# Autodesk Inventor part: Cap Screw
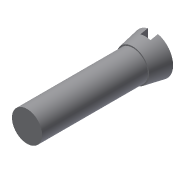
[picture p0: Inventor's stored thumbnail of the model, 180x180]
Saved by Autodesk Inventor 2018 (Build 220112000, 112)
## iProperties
Shininess: 77.0
Length Units: 11269
Angle Units: 11279
Time Units: 11290
Mass Units: 11283
Length Display Precision: 3
Angle Display Precision: 2
Created: 2002-02
Part Number: Cap Screw
Document SubType Name: Modeling
Designer: ***
Density: 1 g/cm^3
Material: Generic
Mass: 0.736586 g
Surface Area: 5.87035 cm^2
Volume: 0.736586 cm^3
Appearance: Default
Density: 0.0
Volumn: 0.0
Area: 0.0
PropertySet Name: Model Information
Control State: 0
Master: False
Checked Out: False
Author: ***
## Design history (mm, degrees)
sketch "Sketch1"
  geometry: L1 (0, 27.83)-(4, 27.83); L2 (4, 27.83)-(3.25, 23.83); L3 (3.25, 23.83)-(0, 23.83); L4 (0, 23.83)-(0, 27.83)
  constraints: 8 end point, 1 horizontal, 1 parallel, 1 perpendicular, 1 point on line
  dimensions: "d2" = 4 distance from line of L1 L2.end; "d5" = 8 diameter of L1.end L4; "d6" = 6.5 diameter of L3.start L4; "d14" = 4 distance of L3.end L1.start
revolve "Revolution1" sketch "Sketch1" stored, may be unused: angle "d7" = 90 deg
sketch "Sketch2"
  geometry: C1 r 3 at (0, 0)
  constraints: 1 centre point
  dimensions: "d8" = 6 diameter of C1
extrude "Extrusion1" join sketch "Sketch2" distance "d9" = 21; taper "d10" = 0 deg
sketch "Sketch3"
  geometry: L1 (-1, 28.967)-(1, 28.967); L2 (1, 28.967)-(1, 26.33); L3 (1, 26.33)-(-1, 26.33); L4 (-1, 26.33)-(-1, 28.967); L5 (-4, 27.83)-(4, 27.83) reference
  constraints: 8 end point, 2 parallel, 1 horizontal, 1 perpendicular
  dimensions: "d11" = 2 distance of L1.start L1.end; "d15" = 1.5 distance between parallel lines of L5 L3
extrude "Extrusion2" cut sketch "Sketch3" extent not by distance; stored distance "d12" = 24; taper "d13" = 0 deg
body "Solid1"
